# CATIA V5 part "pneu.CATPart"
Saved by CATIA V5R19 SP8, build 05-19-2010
Part number: pneu
Bounding box of the stored display mesh (mm): x -10 to 10, y -230 to 230, z -230 to 230
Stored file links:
  G:\EU_thinkMotion\CFAO_2010\SIL_groupe1\SIL_groupe1\A reprendre\scador\monocycle\pneu.CATPart
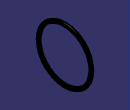
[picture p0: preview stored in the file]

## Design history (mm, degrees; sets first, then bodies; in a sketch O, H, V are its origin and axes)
Parameters
  rayon_roue = 200 mm
Body1 (main body)
  Sketch1 on yz-plane, origin (0, 0, 0), H (0, 1, 0), V (0, 0, 1)
    circle A1 centre (0, 0) radius 200
    radius A1 = 200 {= rayon_roue}
  Sketch2 on zx-plane, origin (0, 0, 0), H (-1, 0, 0), V (0, 0, 1)
    point P1 (-10, 220)
    line L1 (-10, 220) -> (-10, 200.3)
    point P2 (-10, 200.3)
    line L2 (-10, 200.3) -> (-6, 200.3)
    point P3 (-6, 200.3)
    line L3 (-6, 200.3) -> (-6, 220)
    point P4 (-6, 220)
    point P5 (10, 200.3)
    point P6 (10, 220)
    line L4 (10, 220) -> (10, 200.3)
    point P7 (6, 220)
    point P8 (6, 200.3)
    line L5 (6, 200.3) -> (6, 220)
    line L6 (10, 200.3) -> (6, 200.3)
    arc A1 centre (0, 220) radius 6 from (6, 220) to (-6, 220) ccw
    point P9 (0, 220)
    point P10 (6, 220)
    point P11 (-6, 220)
    arc A2 centre (0, 220) radius 10 from (10, 220) to (-10, 220) ccw
    point P12 (10, 220)
    reference projected line E1 (0, -200) -> (0, 200) from Sketch1.A1
    reference projected line E2 (0, -200) -> (0, 200) from Sketch1.A1
    distance E1 L3 = 6
    distance L1 E2 = 10
    distance H P9 = 220 {= rayon_roue +20mm}
    distance L6 H = 200.3 {= rayon_roue+0.3mm}
    vertical: L1 V, L3 V
    horizontal: L2 H
    symmetry: P2 P5 V, P1 P6 V, L1 L4 V, P4 P7 V, P3 P8 V, L3 L5 V, L2 L6 V
    coincidence: P9 V, P11 P4, P6 P12, P7 P10
    tangency: A1 L3, A1 L5, A2 L1, A2 L4
  Rib1: profile Sketch2, centre curve Sketch1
